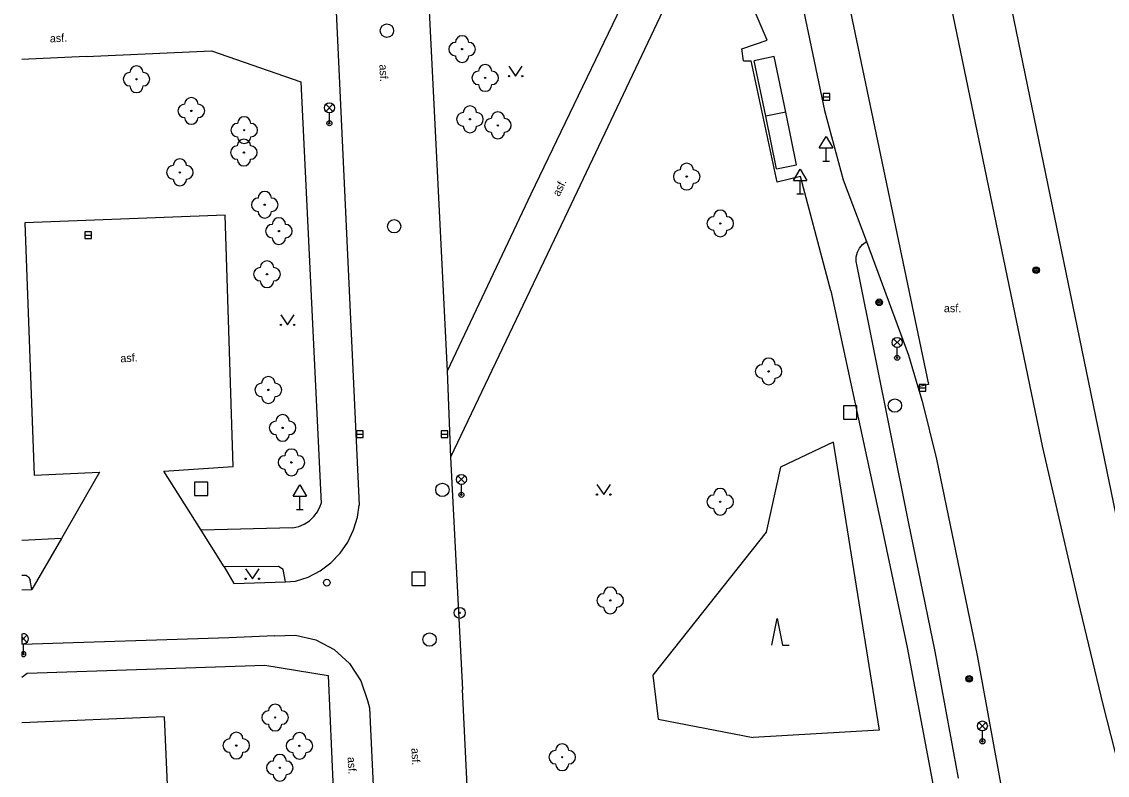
# Model space of a CAD drawing. Extents: x -640201 to -639641, y -1044739 to -1044317.
# Drawn here: x -640198.6 to -640117.2, y -1044489 to -1044432.6 of the extents above; entities that cross this region are included whole.
import ezdxf

# ---------------------------------------------------------------- set-up
doc = ezdxf.new("R2010")
doc.units = 0
for name, color, linetype in [('Budovy', 7, 'Continuous'), ('Pol_bod_pole', 7, 'Continuous'), ('Popis povrchů', 7, 'Continuous'), ('Rozhraní ploch 1', 7, 'Continuous'), ('Rozhraní ploch 2', 7, 'Continuous'), ('Sloupy_označník', 7, 'Continuous'), ('Zeleň - linie', 7, 'Continuous'), ('Zeleň - stromy', 7, 'Continuous'), ('Znaky doprava', 7, 'Continuous'), ('Znaky kanalizace', 7, 'Continuous'), ('Znaky voda', 7, 'Continuous'), ('Značky doprava', 7, 'Continuous'), ('Značky KM', 7, 'Continuous'), ('Šachty ner_', 7, 'Continuous')]:
    doc.layers.add(name, color=color, linetype=linetype)

msp = doc.modelspace()

# ---------------------------------------------------------------- linework, layer by layer
at = {"layer": 'Budovy'}
for p, q in [((-640142.16, -1044435.19), (-640143.66, -1044435.51)), ((-640142.793, -1044439.654), (-640143.66, -1044435.51)), ((-640141.29, -1044439.35), (-640142.16, -1044435.19)), ((-640141.29, -1044439.35), (-640142.793, -1044439.654)), ((-640141.993, -1044443.604), (-640142.793, -1044439.654)), ((-640140.49, -1044443.3), (-640141.29, -1044439.35)), ((-640141.993, -1044443.604), (-640140.49, -1044443.3)), ((-640187.87, -1044484.65), (-640198.551, -1044485.077)), ((-640187.87, -1044484.65), (-640187.4, -1044495.97))]:
    msp.add_line(p, q, dxfattribs=at)
at = {"layer": 'Pol_bod_pole'}
for radius in [0.412, 0.05]:
    msp.add_circle((-640165.73, -1044476.85), radius, dxfattribs=at)
at = {"layer": 'Rozhraní ploch 1'}
for p, q in [((-640175.85, -1044413.58), (-640173.27, -1044468.78)), ((-640101.774, -1044541.352), (-640127.52, -1044416.154)), ((-640168.32, -1044425.88), (-640166.68, -1044458.75)), ((-640147.709, -1044425.85), (-640157.63, -1044446.77)), ((-640141.189, -1044425.917), (-640138.398, -1044439.237)), ((-640151.841, -1044427.726), (-640160.41, -1044445.49)), ((-640129.801, -1044427.138), (-640122.046, -1044464.465)), ((-640142.68, -1044433.95), (-640143.735, -1044431.504)), ((-640144.58, -1044434.62), (-640142.68, -1044433.95)), ((-640193.71, -1044435.19), (-640184.33, -1044434.75)), ((-640184.33, -1044434.75), (-640177.63, -1044437.07)), ((-640144.46, -1044435.52), (-640144.58, -1044434.62)), ((-640193.71, -1044435.19), (-640198.551, -1044435.408)), ((-640144.46, -1044435.52), (-640143.889, -1044435.513)), ((-640141.928, -1044444.6), (-640143.889, -1044435.513)), ((-640177.63, -1044437.07), (-640176.11, -1044468.65)), ((-640138.398, -1044439.237), (-640136.982, -1044444.409)), ((-640140.199, -1044444.18), (-640141.928, -1044444.6)), ((-640137.917, -1044452.737), (-640140.199, -1044444.18)), ((-640136.982, -1044444.409), (-640135.252, -1044449.033)), ((-640160.41, -1044445.49), (-640166.68, -1044458.75)), ((-640183.31, -1044447.06), (-640198.31, -1044447.65)), ((-640182.71, -1044465.9), (-640183.31, -1044447.06)), ((-640157.63, -1044446.77), (-640166.41, -1044465.19)), ((-640198.31, -1044447.65), (-640197.62, -1044466.54)), ((-640135.252, -1044449.033), (-640132.094, -1044457.549)), ((-640132.086, -1044470.025), (-640135.947, -1044450.892)), ((-640137.917, -1044452.737), (-640134.035, -1044470.673)), ((-640166.68, -1044458.75), (-640166.41, -1044465.19)), ((-640131.086, -1044460.994), (-640130.012, -1044465.33)), ((-640122.046, -1044464.465), (-640119.394, -1044476.022)), ((-640166.41, -1044465.19), (-640165.52, -1044482.6)), ((-640187.91, -1044466.23), (-640182.71, -1044465.9)), ((-640130.012, -1044465.33), (-640126.954, -1044480.056)), ((-640197.62, -1044466.54), (-640192.72, -1044466.31)), ((-640192.72, -1044466.31), (-640195.58, -1044471.29)), ((-640185.1, -1044470.66), (-640187.91, -1044466.23)), ((-640130.099, -1044479.737), (-640132.086, -1044470.025)), ((-640178.24, -1044470.48), (-640185.1, -1044470.66)), ((-640183.38, -1044473.4), (-640185.1, -1044470.66)), ((-640134.035, -1044470.673), (-640132.19, -1044479.447)), ((-640195.58, -1044471.29), (-640198.551, -1044471.433)), ((-640195.58, -1044471.29), (-640197.8, -1044475.11)), ((-640179.3, -1044473.37), (-640183.38, -1044473.4)), ((-640183.38, -1044473.4), (-640182.658, -1044474.657)), ((-640178.96, -1044473.6), (-640179.3, -1044473.37)), ((-640198.19, -1044474.06), (-640198.551, -1044474.065)), ((-640178.79, -1044474.52), (-640178.96, -1044473.6)), ((-640197.8, -1044475.11), (-640197.93, -1044474.4)), ((-640182.658, -1044474.657), (-640178.79, -1044474.52)), ((-640178.79, -1044474.52), (-640178.03, -1044474.49)), ((-640198.551, -1044475.136), (-640197.8, -1044475.11)), ((-640119.394, -1044476.022), (-640117.535, -1044483.704)), ((-640183.04, -1044478.72), (-640198.551, -1044479.21)), ((-640179.59, -1044478.58), (-640183.04, -1044478.72)), ((-640132.19, -1044479.447), (-640130.281, -1044489.666)), ((-640128.345, -1044489.243), (-640130.099, -1044479.737)), ((-640126.954, -1044480.056), (-640124.989, -1044490.829)), ((-640198.551, -1044481.667), (-640198.15, -1044481.37)), ((-640198.15, -1044481.37), (-640189.96, -1044481.09)), ((-640189.96, -1044481.09), (-640180.32, -1044480.76)), ((-640180.32, -1044480.76), (-640175.58, -1044481.54)), ((-640175.58, -1044481.54), (-640175.21, -1044490.07)), ((-640164.48, -1044504.16), (-640165.52, -1044482.6)), ((-640172.49, -1044483.97), (-640171.53, -1044504.12)), ((-640117.535, -1044483.704), (-640108.638, -1044518.358))]:
    msp.add_line(p, q, dxfattribs=at)
for points in [[(-640135.947, -1044450.892), (-640136.021, -1044450.545), (-640136.015, -1044450.191), (-640135.931, -1044449.846), (-640135.772, -1044449.529), (-640135.546, -1044449.256), (-640135.252, -1044449.033)], [(-640132.094, -1044457.549), (-640131.402, -1044459.916), (-640131.086, -1044460.994)], [(-640178.24, -1044470.48), (-640177.796, -1044470.378), (-640177.377, -1044470.2), (-640176.996, -1044469.951), (-640176.663, -1044469.639), (-640176.391, -1044469.275), (-640176.186, -1044468.868), (-640176.11, -1044468.65)], [(-640178.03, -1044474.49), (-640177.079, -1044474.168), (-640176.19, -1044473.7), (-640175.388, -1044473.097), (-640174.691, -1044472.374), (-640174.117, -1044471.55), (-640173.681, -1044470.645), (-640173.395, -1044469.683), (-640173.27, -1044468.78)], [(-640198.19, -1044474.06), (-640198.04, -1044474.164), (-640197.947, -1044474.322), (-640197.93, -1044474.4)], [(-640179.59, -1044478.58), (-640178.034, -1044478.527), (-640176.515, -1044478.87), (-640175.133, -1044479.587), (-640173.979, -1044480.632), (-640173.127, -1044481.935), (-640172.634, -1044483.412), (-640172.49, -1044483.97)]]:
    msp.add_lwpolyline(points, dxfattribs=at)
at = {"layer": 'Rozhraní ploch 2'}
for p, q in [((-640137.78, -1044425.48), (-640130.61, -1044459.75)), ((-640130.61, -1044459.75), (-640131.402, -1044459.916))]:
    msp.add_line(p, q, dxfattribs=at)
at = {"layer": 'Sloupy_označník'}
for centre, radius in [((-640122.531, -1044451.183), 0.25), ((-640122.531, -1044451.183), 0.158), ((-640122.531, -1044451.183), 0.05), ((-640134.303, -1044453.593), 0.25), ((-640134.303, -1044453.593), 0.158), ((-640134.303, -1044453.593), 0.05), ((-640127.552, -1044481.787), 0.25), ((-640127.552, -1044481.787), 0.158), ((-640127.552, -1044481.787), 0.05)]:
    msp.add_circle(centre, radius, dxfattribs=at)
at = {"layer": 'Zeleň - linie'}
for p, q in [((-640137.74, -1044464.07), (-640141.69, -1044465.95)), ((-640137.74, -1044464.07), (-640134.29, -1044485.64)), ((-640141.69, -1044465.95), (-640142.77, -1044470.82)), ((-640142.77, -1044470.82), (-640151.25, -1044481.51)), ((-640151.25, -1044481.51), (-640150.85, -1044484.82)), ((-640150.85, -1044484.82), (-640143.75, -1044486.18)), ((-640134.29, -1044485.64), (-640143.75, -1044486.18))]:
    msp.add_line(p, q, dxfattribs=at)
at = {"layer": 'Zeleň - stromy'}
for centre in [(-640165.55, -1044434.63), (-640163.82, -1044436.79), (-640189.95, -1044436.89), (-640185.84, -1044439.26), (-640164.96, -1044439.89), (-640181.88, -1044440.7), (-640162.87, -1044440.34), (-640181.9, -1044442.38), (-640186.7, -1044443.86), (-640148.72, -1044444.18), (-640180.34, -1044446.29), (-640146.2, -1044447.69), (-640179.28, -1044448.26), (-640180.17, -1044451.49), (-640142.58, -1044458.77), (-640180.07, -1044460.16), (-640179, -1044463), (-640178.34, -1044465.58), (-640146.21, -1044468.53), (-640154.45, -1044475.92), (-640179.56, -1044484.69), (-640182.47, -1044486.79), (-640177.74, -1044486.81), (-640158.05, -1044487.66), (-640179.21, -1044488.45)]:
    msp.add_circle(centre, 0.05, dxfattribs=at)
for centre, start, end in [((-640166.05, -1044434.63), 90, 270), ((-640165.55, -1044434.13), 0, 180), ((-640165.05, -1044434.63), 270, 90), ((-640165.55, -1044435.13), 180, 0), ((-640189.95, -1044436.39), 0, 180), ((-640163.82, -1044436.29), 0, 180), ((-640190.45, -1044436.89), 90, 270), ((-640189.45, -1044436.89), 270, 90), ((-640164.32, -1044436.79), 90, 270), ((-640163.32, -1044436.79), 270, 90), ((-640189.95, -1044437.39), 180, 0), ((-640163.82, -1044437.29), 180, 0), ((-640185.84, -1044438.76), 0, 180), ((-640186.34, -1044439.26), 90, 270), ((-640185.34, -1044439.26), 270, 90), ((-640164.96, -1044439.39), 0, 180), ((-640185.84, -1044439.76), 180, 0), ((-640181.88, -1044440.2), 0, 180), ((-640165.46, -1044439.89), 90, 270), ((-640164.46, -1044439.89), 270, 90), ((-640163.37, -1044440.34), 90, 270), ((-640162.87, -1044439.84), 0, 180), ((-640162.37, -1044440.34), 270, 90), ((-640182.38, -1044440.7), 90, 270), ((-640181.38, -1044440.7), 270, 90), ((-640164.96, -1044440.39), 180, 0), ((-640162.87, -1044440.84), 180, 0), ((-640181.9, -1044441.88), 0, 180), ((-640181.88, -1044441.2), 180, 0), ((-640182.4, -1044442.38), 90, 270), ((-640181.4, -1044442.38), 270, 90), ((-640186.7, -1044443.36), 0, 180), ((-640181.9, -1044442.88), 180, 0), ((-640148.72, -1044443.68), 0, 180), ((-640187.2, -1044443.86), 90, 270), ((-640186.2, -1044443.86), 270, 90), ((-640149.22, -1044444.18), 90, 270), ((-640148.22, -1044444.18), 270, 90), ((-640186.7, -1044444.36), 180, 0), ((-640148.72, -1044444.68), 180, 0), ((-640180.34, -1044445.79), 0, 180), ((-640180.84, -1044446.29), 90, 270), ((-640179.84, -1044446.29), 270, 90), ((-640180.34, -1044446.79), 180, 0), ((-640179.28, -1044447.76), 0, 180), ((-640146.7, -1044447.69), 90, 270), ((-640146.2, -1044447.19), 0, 180), ((-640145.7, -1044447.69), 270, 90), ((-640179.78, -1044448.26), 90, 270), ((-640178.78, -1044448.26), 270, 90), ((-640146.2, -1044448.19), 180, 0), ((-640179.28, -1044448.76), 180, 0), ((-640180.17, -1044450.99), 0, 180), ((-640180.67, -1044451.49), 90, 270), ((-640179.67, -1044451.49), 270, 90), ((-640180.17, -1044451.99), 180, 0), ((-640142.58, -1044458.27), 0, 180), ((-640143.08, -1044458.77), 90, 270), ((-640142.08, -1044458.77), 270, 90), ((-640180.07, -1044459.66), 0, 180), ((-640142.58, -1044459.27), 180, 0), ((-640180.57, -1044460.16), 90, 270), ((-640179.57, -1044460.16), 270, 90), ((-640180.07, -1044460.66), 180, 0), ((-640179, -1044462.5), 0, 180), ((-640179.5, -1044463), 90, 270), ((-640178.5, -1044463), 270, 90), ((-640179, -1044463.5), 180, 0), ((-640178.84, -1044465.58), 90, 270), ((-640178.34, -1044465.08), 0, 180), ((-640177.84, -1044465.58), 270, 90), ((-640178.34, -1044466.08), 180, 0), ((-640146.21, -1044468.03), 0, 180), ((-640146.71, -1044468.53), 90, 270), ((-640145.71, -1044468.53), 270, 90), ((-640146.21, -1044469.03), 180, 0), ((-640154.45, -1044475.42), 0, 180), ((-640154.95, -1044475.92), 90, 270), ((-640153.95, -1044475.92), 270, 90), ((-640154.45, -1044476.42), 180, 0), ((-640179.56, -1044484.19), 0, 180), ((-640180.06, -1044484.69), 90, 270), ((-640179.06, -1044484.69), 270, 90), ((-640179.56, -1044485.19), 180, 0), ((-640182.97, -1044486.79), 90, 270), ((-640182.47, -1044486.29), 0, 180), ((-640181.97, -1044486.79), 270, 90), ((-640178.24, -1044486.81), 90, 270), ((-640177.74, -1044486.31), 0, 180), ((-640177.24, -1044486.81), 270, 90), ((-640158.55, -1044487.66), 90, 270), ((-640158.05, -1044487.16), 0, 180), ((-640157.55, -1044487.66), 270, 90), ((-640182.47, -1044487.29), 180, 0), ((-640179.71, -1044488.45), 90, 270), ((-640179.21, -1044487.95), 0, 180), ((-640178.71, -1044488.45), 270, 90), ((-640177.74, -1044487.31), 180, 0), ((-640158.05, -1044488.16), 180, 0), ((-640179.21, -1044488.95), 180, 0)]:
    msp.add_arc(centre, 0.5, start, end, dxfattribs=at)
at = {"layer": 'Znaky doprava'}
for p, q in [((-640175.755, -1044438.765), (-640175.225, -1044439.295)), ((-640175.755, -1044439.295), (-640175.225, -1044438.765)), ((-640175.49, -1044440.18), (-640175.49, -1044439.405)), ((-640133.214, -1044456.334), (-640132.684, -1044456.864)), ((-640133.214, -1044456.864), (-640132.684, -1044456.334)), ((-640132.949, -1044457.749), (-640132.949, -1044456.974)), ((-640165.865, -1044466.595), (-640165.335, -1044467.125)), ((-640165.865, -1044467.125), (-640165.335, -1044466.595)), ((-640165.6, -1044468.01), (-640165.6, -1044467.235)), ((-640198.551, -1044478.921), (-640198.155, -1044478.525)), ((-640198.551, -1044478.659), (-640198.155, -1044479.055)), ((-640198.42, -1044479.94), (-640198.42, -1044479.165)), ((-640126.827, -1044485.058), (-640126.297, -1044485.588)), ((-640126.827, -1044485.588), (-640126.297, -1044485.058)), ((-640126.562, -1044486.473), (-640126.562, -1044485.698))]:
    msp.add_line(p, q, dxfattribs=at)
for points in [[(-640198.551, -1044478.439), (-640198.551, -1044479.141)], [(-640198.551, -1044479.803), (-640198.551, -1044480.077)]]:
    msp.add_lwpolyline(points, dxfattribs=at)
for centre, radius in [((-640175.49, -1044439.03), 0.375), ((-640175.49, -1044440.18), 0.19), ((-640175.49, -1044440.18), 0.05), ((-640132.949, -1044456.599), 0.375), ((-640132.949, -1044457.749), 0.19), ((-640132.949, -1044457.749), 0.05), ((-640165.6, -1044466.86), 0.375), ((-640165.6, -1044468.01), 0.19), ((-640165.6, -1044468.01), 0.05), ((-640198.42, -1044479.94), 0.05), ((-640126.562, -1044485.323), 0.375), ((-640126.562, -1044486.473), 0.19), ((-640126.562, -1044486.473), 0.05)]:
    msp.add_circle(centre, radius, dxfattribs=at)
for centre, radius, start, end in [((-640198.42, -1044478.79), 0.375, 249.52847, 110.47153), ((-640198.42, -1044479.94), 0.19, 226.3477, 133.6523)]:
    msp.add_arc(centre, radius, start, end, dxfattribs=at)
at = {"layer": 'Znaky kanalizace'}
for p, q in [((-640138.489, -1044438.212), (-640137.989, -1044438.212)), ((-640193.83, -1044448.56), (-640193.33, -1044448.56)), ((-640131.287, -1044459.989), (-640130.787, -1044459.989)), ((-640173.47, -1044463.47), (-640172.97, -1044463.47)), ((-640167.13, -1044463.48), (-640166.63, -1044463.48))]:
    msp.add_line(p, q, dxfattribs=at)
for points in [[(-640138.489, -1044438.462), (-640137.989, -1044438.462), (-640137.989, -1044437.962), (-640138.489, -1044437.962)], [(-640193.83, -1044448.81), (-640193.33, -1044448.81), (-640193.33, -1044448.31), (-640193.83, -1044448.31)], [(-640131.287, -1044460.239), (-640130.787, -1044460.239), (-640130.787, -1044459.739), (-640131.287, -1044459.739)], [(-640173.47, -1044463.72), (-640172.97, -1044463.72), (-640172.97, -1044463.22), (-640173.47, -1044463.22)], [(-640167.13, -1044463.73), (-640166.63, -1044463.73), (-640166.63, -1044463.23), (-640167.13, -1044463.23)]]:
    msp.add_lwpolyline(points, close=True, dxfattribs=at)
for centre in [(-640171.18, -1044433.25), (-640170.64, -1044447.9), (-640133.115, -1044461.326), (-640167.03, -1044467.64), (-640167.99, -1044478.85)]:
    msp.add_circle(centre, 0.5, dxfattribs=at)
at = {"layer": 'Znaky voda'}
msp.add_circle((-640175.68, -1044474.59), 0.25, dxfattribs=at)
at = {"layer": 'Značky doprava'}
for p, q in [((-640138.78, -1044442.03), (-640138.28, -1044441.18)), ((-640138.28, -1044441.18), (-640137.78, -1044442.03)), ((-640138.78, -1044442.03), (-640137.78, -1044442.03)), ((-640138.28, -1044443.03), (-640138.28, -1044442.03)), ((-640138.53, -1044443.03), (-640138.03, -1044443.03)), ((-640140.71, -1044444.47), (-640140.21, -1044443.62)), ((-640140.21, -1044443.62), (-640139.71, -1044444.47)), ((-640140.71, -1044444.47), (-640139.71, -1044444.47)), ((-640140.21, -1044445.47), (-640140.21, -1044444.47)), ((-640140.46, -1044445.47), (-640139.96, -1044445.47)), ((-640178.2, -1044468.11), (-640177.7, -1044467.26)), ((-640177.7, -1044467.26), (-640177.2, -1044468.11)), ((-640178.2, -1044468.11), (-640177.2, -1044468.11)), ((-640177.7, -1044469.11), (-640177.7, -1044468.11)), ((-640177.95, -1044469.11), (-640177.45, -1044469.11))]:
    msp.add_line(p, q, dxfattribs=at)
at = {"layer": 'Značky KM'}
for p, q in [((-640162.045, -1044435.908), (-640161.545, -1044436.658)), ((-640161.545, -1044436.658), (-640161.045, -1044435.908)), ((-640179.135, -1044454.538), (-640178.635, -1044455.288)), ((-640178.635, -1044455.288), (-640178.135, -1044454.538)), ((-640155.441, -1044467.249), (-640154.941, -1044467.999)), ((-640154.941, -1044467.999), (-640154.441, -1044467.249)), ((-640181.769, -1044473.548), (-640181.269, -1044474.298)), ((-640181.269, -1044474.298), (-640180.769, -1044473.548)), ((-640142.339, -1044479.264), (-640141.939, -1044477.264)), ((-640141.939, -1044477.264), (-640141.539, -1044479.264)), ((-640141.539, -1044479.264), (-640141.039, -1044479.264))]:
    msp.add_line(p, q, dxfattribs=at)
for centre in [(-640162.045, -1044436.658), (-640161.045, -1044436.658), (-640179.135, -1044455.288), (-640178.135, -1044455.288), (-640155.441, -1044467.999), (-640154.441, -1044467.999), (-640181.769, -1044474.298), (-640180.769, -1044474.298)]:
    msp.add_circle(centre, 0.05, dxfattribs=at)
at = {"layer": 'Šachty ner_'}
for points in [[(-640136.96, -1044462.34), (-640135.96, -1044462.34), (-640135.96, -1044461.34), (-640136.96, -1044461.34)], [(-640185.6, -1044468.07), (-640184.6, -1044468.07), (-640184.6, -1044467.07), (-640185.6, -1044467.07)], [(-640169.32, -1044474.8), (-640168.32, -1044474.8), (-640168.32, -1044473.8), (-640169.32, -1044473.8)]]:
    msp.add_lwpolyline(points, close=True, dxfattribs=at)

# ---------------------------------------------------------------- texts
at = {"layer": 'Popis povrchů'}
for rotation, p in [(2.57868, (-640196.43, -1044434.131)), (272.67601, (-640171.748, -1044435.79)), (64.62805, (-640158.265, -1044445.714)), (3.63121, (-640191.139, -1044458.099)), (272.72766, (-640169.352, -1044486.986)), (273.39674, (-640174.135, -1044487.658))]:
    msp.add_text('asf.', height=0.6, rotation=rotation, dxfattribs=at).set_placement(p)
msp.add_text('asf.', height=0.6, dxfattribs=at).set_placement((-640129.443, -1044454.334))

doc.saveas('drawing.dxf')
